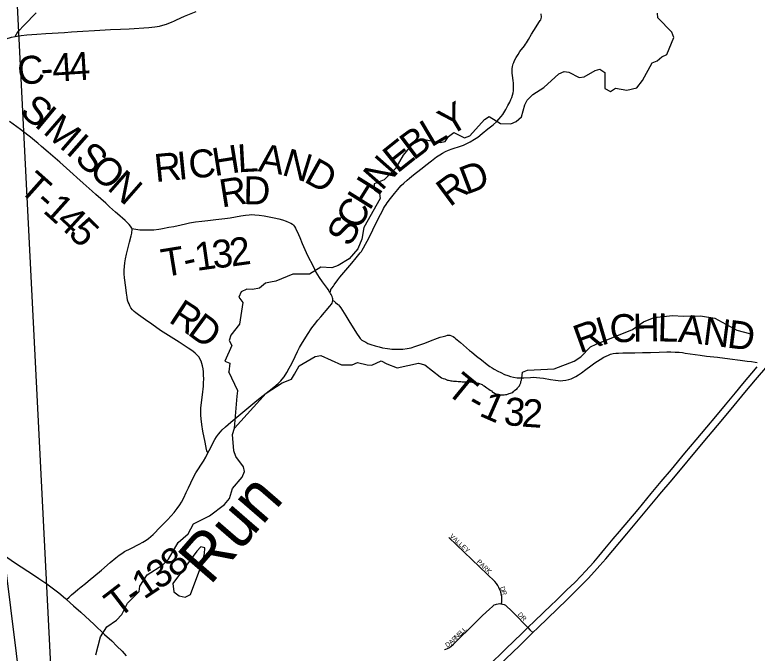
# Model space of a CAD drawing. Extents: x -19.5 to 44.1, y 0 to 22.
# Drawn here: x -16.656 to -15.147, y 16.812 to 18.108 of the extents above; entities that cross this region are included whole.
import ezdxf

# ---------------------------------------------------------------- set-up
doc = ezdxf.new("R2010")
doc.units = 0
for name, color, linetype in [('GM_X_County_Road', 7, 'Continuous'), ('GM_X_County_Road_Text', 7, 'Continuous'), ('GM_X_Minor_Lake', 7, 'Continuous'), ('GM_X_Minor_River', 7, 'Continuous'), ('GM_X_Minor_River_Text', 7, 'Continuous'), ('GM_X_State_Route', 7, 'Continuous'), ('GM_X_Township_Road', 7, 'Continuous'), ('GM_X_Township_Road_Text', 7, 'Continuous'), ('GM_X_Township_Subdivision', 7, 'Continuous'), ('GM_X_Township_Subdivision_Text', 7, 'Continuous'), ('GM_X_US_Route', 7, 'Continuous'), ('SH_Text', 7, 'Continuous')]:
    doc.layers.add(name, color=color, linetype=linetype)

msp = doc.modelspace()

# ---------------------------------------------------------------- linework, layer by layer
at = {"layer": 'GM_X_County_Road'}
for points in [[(-16.655, 18.0643), (-16.6513, 18.065), (-16.6427, 18.0663), (-16.6315, 18.0675), (-16.6111, 18.0691), (-16.5931, 18.0703), (-16.5548, 18.0728), (-16.5405, 18.0737), (-16.5176, 18.0753), (-16.494, 18.0767), (-16.4618, 18.0785), (-16.4413, 18.0793), (-16.4239, 18.0802), (-16.3836, 18.0827), (-16.3713, 18.0839), (-16.3622, 18.0855), (-16.355, 18.0873), (-16.348, 18.0896), (-16.3365, 18.0942), (-16.3325, 18.0959), (-16.3275, 18.0983), (-16.311, 18.1054), (-16.2876, 18.1155)], [(-16.8237, 18.0111), (-16.8025, 18.0178), (-16.7647, 18.0298), (-16.7263, 18.0425), (-16.7151, 18.0462), (-16.6944, 18.0528), (-16.6735, 18.0597), (-16.6626, 18.0629), (-16.655, 18.0643)]]:
    msp.add_lwpolyline(points, dxfattribs=at)
at = {"layer": 'GM_X_Minor_Lake'}
for points in [[(-16.3349, 16.9533), (-16.333, 16.9365), (-16.3218, 16.9279), (-16.3097, 16.9254), (-16.2989, 16.9312), (-16.2761, 16.9927), (-16.2708, 17.0135), (-16.2701, 17.0256), (-16.2777, 17.028), (-16.2862, 17.0191)], [(-16.2862, 17.0191), (-16.3349, 16.9533)]]:
    msp.add_lwpolyline(points, dxfattribs=at)
at = {"layer": 'GM_X_Minor_River'}
for points in [[(-15.9051, 17.7734), (-15.8808, 17.7974), (-15.8659, 17.8237), (-15.8477, 17.8458), (-15.8278, 17.8557), (-15.7918, 17.8494), (-15.7815, 17.8511), (-15.7745, 17.8613), (-15.7641, 17.8691), (-15.7423, 17.8588), (-15.7312, 17.8624), (-15.7018, 17.8961), (-15.6918, 17.902), (-15.6693, 17.8876), (-15.648, 17.8868), (-15.6369, 17.8916), (-15.6261, 17.9013), (-15.6196, 17.9255), (-15.6149, 17.9352), (-15.603, 17.9464), (-15.5807, 17.9605), (-15.5502, 17.9888), (-15.5399, 17.9932), (-15.53, 17.9919), (-15.5093, 17.9809), (-15.4991, 17.9826), (-15.4768, 17.9955), (-15.4669, 17.998), (-15.4572, 17.991), (-15.4573, 17.9591), (-15.4457, 17.9529), (-15.4353, 17.9595), (-15.4126, 17.9553), (-15.392, 17.9603), (-15.3807, 17.9749), (-15.3611, 18.011), (-15.3508, 18.015), (-15.3412, 18.0228), (-15.3312, 18.0276), (-15.3166, 18.0627), (-15.3206, 18.0734), (-15.3493, 18.102), (-15.3503, 18.1115)], [(-15.9051, 17.7734), (-15.9256, 17.7653), (-15.9251, 17.7531), (-15.9146, 17.7453), (-15.9137, 17.7354), (-15.9467, 17.6765), (-15.9509, 17.653), (-15.9589, 17.6334), (-15.9767, 17.6126), (-15.999, 17.599), (-16.0116, 17.5947), (-16.0343, 17.596), (-16.0573, 17.5816), (-16.0911, 17.5816), (-16.1255, 17.5676), (-16.1365, 17.5651), (-16.1464, 17.5635), (-16.1584, 17.5535), (-16.1732, 17.5504), (-16.1846, 17.5514), (-16.1961, 17.5459), (-16.2009, 17.5346), (-16.1927, 17.5242), (-16.1992, 17.4803), (-16.2167, 17.4575), (-16.2204, 17.447), (-16.2149, 17.437), (-16.2295, 17.405), (-16.219, 17.4006), (-16.2209, 17.3832)], [(-15.6257, 17.3704), (-15.6244, 17.3825), (-15.614, 17.3865), (-15.5601, 17.3894), (-15.5192, 17.405), (-15.5058, 17.4135), (-15.4864, 17.4337), (-15.4749, 17.4392), (-15.4008, 17.4694), (-15.3781, 17.485), (-15.3571, 17.4938), (-15.3198, 17.4977), (-15.2974, 17.4965), (-15.2625, 17.4967), (-15.2337, 17.4924), (-15.1885, 17.4681), (-15.1632, 17.4612)], [(-16.0879, 17.3788), (-16.0783, 17.3952), (-16.0457, 17.4147), (-16.0343, 17.4167), (-15.9918, 17.3975), (-15.9706, 17.3975), (-15.9599, 17.4022), (-15.9398, 17.3972), (-15.9304, 17.3966), (-15.9112, 17.4056)], [(-15.9112, 17.4056), (-15.9001, 17.3994), (-15.879, 17.3911), (-15.8359, 17.401), (-15.8227, 17.3977), (-15.7917, 17.3733)], [(-16.4911, 16.8084), (-16.482, 16.8451), (-16.4687, 16.8653), (-16.4491, 16.879), (-16.4386, 16.8905), (-16.4272, 16.9131), (-16.4035, 16.9373), (-16.4022, 16.9479), (-16.387, 16.9707), (-16.3554, 16.9913), (-16.3438, 17.0029), (-16.3242, 17.0366), (-16.3034, 17.0541), (-16.2927, 17.0747), (-16.2605, 17.0904), (-16.2297, 17.114), (-16.22, 17.126), (-16.2135, 17.146), (-16.1941, 17.1691), (-16.1893, 17.1808), (-16.191, 17.1903), (-16.2066, 17.2112), (-16.2109, 17.223), (-16.2133, 17.2558), (-16.2096, 17.2686), (-16.2042, 17.3335), (-16.2028, 17.3445), (-16.2209, 17.3832)], [(-16.2096, 17.2686), (-16.1449, 17.3398), (-16.1129, 17.3608), (-16.0934, 17.3683), (-16.0879, 17.3788)], [(-15.7917, 17.3733), (-15.7888, 17.3711), (-15.7854, 17.3695), (-15.782, 17.3687), (-15.7797, 17.3676), (-15.777, 17.3664), (-15.7748, 17.366), (-15.7721, 17.3656), (-15.7702, 17.3652), (-15.7672, 17.3648), (-15.7645, 17.3644), (-15.7615, 17.3644), (-15.7584, 17.3644), (-15.755, 17.3636), (-15.752, 17.3636), (-15.7493, 17.3636), (-15.747, 17.3632), (-15.7444, 17.3632), (-15.7409, 17.3631), (-15.7379, 17.3635), (-15.7348, 17.3631), (-15.7318, 17.3627), (-15.7291, 17.3627), (-15.7269, 17.3623), (-15.7246, 17.3619), (-15.7219, 17.3619), (-15.7193, 17.3611), (-15.7166, 17.3603), (-15.714, 17.3599), (-15.7064, 17.3572), (-15.7041, 17.3556), (-15.7022, 17.3549), (-15.6992, 17.3529), (-15.6965, 17.3507), (-15.6946, 17.3495), (-15.6927, 17.3483), (-15.6897, 17.346), (-15.6874, 17.3449), (-15.6852, 17.3422), (-15.6833, 17.3414), (-15.6799, 17.3391), (-15.6765, 17.338), (-15.6734, 17.3372), (-15.6708, 17.3372), (-15.6689, 17.3368), (-15.6658, 17.3367), (-15.6639, 17.3367), (-15.6613, 17.3367), (-15.6586, 17.3371), (-15.6559, 17.3374), (-15.6517, 17.3389), (-15.6487, 17.34), (-15.6464, 17.3404), (-15.6441, 17.3412), (-15.6426, 17.3434), (-15.6407, 17.3453), (-15.638, 17.3472), (-15.6361, 17.3479), (-15.6346, 17.3498), (-15.6338, 17.3517), (-15.6307, 17.3551), (-15.6299, 17.357), (-15.628, 17.3608), (-15.6276, 17.3638), (-15.6265, 17.3665), (-15.6257, 17.3704)]]:
    msp.add_lwpolyline(points, dxfattribs=at)
at = {"layer": 'GM_X_State_Route'}
for points in [[(-16.679, 17.0112), (-16.6547, 16.9949), (-16.618, 16.9709)], [(-16.618, 16.9709), (-16.6069, 16.9636), (-16.591, 16.9526), (-16.58, 16.9445), (-16.5668, 16.9341), (-16.553, 16.9226), (-16.5508, 16.9207), (-16.5368, 16.9081), (-16.522, 16.8949), (-16.495, 16.87), (-16.4738, 16.85), (-16.4591, 16.8366), (-16.4483, 16.8262), (-16.4379, 16.8156), (-16.4294, 16.8064)]]:
    msp.add_lwpolyline(points, dxfattribs=at)
at = {"layer": 'GM_X_Township_Road'}
for points in [[(-16.655, 18.0643), (-16.6525, 18.0689), (-16.6515, 18.0708), (-16.6499, 18.0732), (-16.6482, 18.0754), (-16.6367, 18.0876), (-16.6125, 18.1126)], [(-16.015, 17.5439), (-16.0147, 17.5465), (-16.014, 17.5489), (-16.0135, 17.5503), (-16.0115, 17.5534), (-16.0086, 17.5575), (-16.0068, 17.5598), (-15.9993, 17.5701), (-15.9952, 17.5755), (-15.9875, 17.5847), (-15.971, 17.6042), (-15.9623, 17.6148), (-15.9541, 17.6248), (-15.9517, 17.6278), (-15.9499, 17.6304), (-15.9471, 17.6351), (-15.9359, 17.656), (-15.9282, 17.6716), (-15.9168, 17.6951), (-15.909, 17.7106), (-15.9065, 17.7149), (-15.9044, 17.7184), (-15.9015, 17.7229), (-15.8991, 17.7267), (-15.8927, 17.7354), (-15.8844, 17.7456), (-15.8776, 17.7536), (-15.8747, 17.7569), (-15.8707, 17.7616), (-15.8654, 17.7668), (-15.859, 17.7726), (-15.8542, 17.7766), (-15.846, 17.7837), (-15.8399, 17.7884), (-15.8285, 17.7969), (-15.8207, 17.803), (-15.8095, 17.8119), (-15.7991, 17.8198), (-15.7925, 17.8243), (-15.7871, 17.8275), (-15.7811, 17.8307), (-15.7748, 17.8334), (-15.7672, 17.8361), (-15.7502, 17.8416), (-15.7445, 17.8436), (-15.7377, 17.8468), (-15.7304, 17.8506), (-15.7221, 17.8557), (-15.7152, 17.8602), (-15.706, 17.8675), (-15.6948, 17.8767), (-15.6841, 17.885), (-15.6766, 17.892), (-15.6725, 17.8964), (-15.6678, 17.9018), (-15.6644, 17.9062), (-15.658, 17.9164), (-15.6538, 17.9242), (-15.6503, 17.9312), (-15.6478, 17.9362), (-15.646, 17.9403), (-15.6444, 17.9452), (-15.6434, 17.9497), (-15.6427, 17.9541), (-15.6425, 17.9565), (-15.6425, 17.9584), (-15.6426, 17.9623), (-15.6427, 17.9647), (-15.6427, 17.9668), (-15.6429, 17.9697), (-15.6436, 17.9753), (-15.6448, 17.9849), (-15.6455, 17.9899), (-15.6456, 17.9949), (-15.6455, 17.9989), (-15.6447, 18.0033), (-15.6432, 18.0086), (-15.6421, 18.0115), (-15.6403, 18.0157), (-15.6369, 18.0221), (-15.6334, 18.0277), (-15.6294, 18.034), (-15.6201, 18.0456), (-15.6179, 18.0487), (-15.616, 18.0516), (-15.612, 18.0581), (-15.6059, 18.069), (-15.6014, 18.0766), (-15.5897, 18.0947), (-15.5884, 18.0967), (-15.5872, 18.0985), (-15.5862, 18.1011), (-15.5857, 18.1034), (-15.5858, 18.1058), (-15.5861, 18.1083), (-15.5867, 18.1104)], [(-16.4181, 17.6742), (-16.4183, 17.6749), (-16.4193, 17.677), (-16.4209, 17.6792), (-16.4236, 17.6824), (-16.426, 17.685), (-16.4286, 17.6873), (-16.4319, 17.6905), (-16.4372, 17.6953), (-16.4421, 17.6995), (-16.447, 17.7042), (-16.4512, 17.7079), (-16.4632, 17.7187), (-16.4712, 17.7256), (-16.4916, 17.7437), (-16.4985, 17.75), (-16.517, 17.7666), (-16.5301, 17.778), (-16.5375, 17.7846), (-16.5642, 17.8089), (-16.5739, 17.8176), (-16.5879, 17.8296), (-16.6017, 17.8412), (-16.6094, 17.8479), (-16.6153, 17.8528), (-16.6209, 17.8573), (-16.6443, 17.8753), (-16.6665, 17.8916)], [(-16.4181, 17.6742), (-16.4144, 17.6736), (-16.41, 17.6729), (-16.4061, 17.6723), (-16.4021, 17.6717), (-16.3983, 17.6715), (-16.3896, 17.6714), (-16.3809, 17.6715), (-16.3734, 17.6719), (-16.3636, 17.673), (-16.3593, 17.6735), (-16.3557, 17.6741), (-16.3429, 17.6768), (-16.3331, 17.6785), (-16.3182, 17.6818), (-16.3091, 17.6841), (-16.301, 17.686), (-16.2889, 17.6879), (-16.2759, 17.6892), (-16.2635, 17.6907), (-16.2476, 17.6924), (-16.2295, 17.6947), (-16.2186, 17.696), (-16.1969, 17.7001), (-16.1872, 17.7017), (-16.1799, 17.7025), (-16.1743, 17.7027), (-16.1681, 17.7025), (-16.1595, 17.7017), (-16.1492, 17.7001), (-16.1291, 17.6961), (-16.1196, 17.6942), (-16.1123, 17.6919), (-16.1046, 17.6895), (-16.0982, 17.6869), (-16.0948, 17.6855), (-16.0915, 17.6835), (-16.0896, 17.6815), (-16.0874, 17.6783), (-16.0855, 17.6748), (-16.0797, 17.6623), (-16.077, 17.6559), (-16.0722, 17.644), (-16.0609, 17.6196), (-16.05, 17.5976), (-16.044, 17.5856), (-16.0411, 17.5802), (-16.0378, 17.5749), (-16.0313, 17.5659), (-16.0215, 17.5522), (-16.0181, 17.5476), (-16.0169, 17.546), (-16.015, 17.5439)], [(-16.2635, 17.2185), (-16.2646, 17.2206), (-16.2658, 17.2228), (-16.2664, 17.2256), (-16.2693, 17.2401), (-16.2737, 17.2628), (-16.2756, 17.2762), (-16.2772, 17.2877), (-16.2778, 17.2951), (-16.278, 17.302), (-16.2778, 17.3091), (-16.2757, 17.3263), (-16.2746, 17.3367), (-16.2726, 17.3544), (-16.2722, 17.3612), (-16.2717, 17.3688), (-16.2722, 17.3764), (-16.2724, 17.3832), (-16.2733, 17.3896), (-16.2744, 17.3953), (-16.2756, 17.4001), (-16.2772, 17.4047), (-16.2797, 17.4098), (-16.2816, 17.4128), (-16.2839, 17.4158), (-16.2861, 17.4181), (-16.2894, 17.4212), (-16.2933, 17.4243), (-16.2981, 17.4276), (-16.3036, 17.4313), (-16.322, 17.4434), (-16.3599, 17.4674), (-16.3776, 17.4799), (-16.3905, 17.4888), (-16.4044, 17.4988), (-16.4099, 17.5031), (-16.4134, 17.5058), (-16.4165, 17.5089), (-16.4199, 17.5133), (-16.422, 17.5172), (-16.4237, 17.5212), (-16.4254, 17.525), (-16.4267, 17.5288), (-16.4279, 17.5351), (-16.4289, 17.543), (-16.4303, 17.5548), (-16.433, 17.574), (-16.4334, 17.5822), (-16.4337, 17.5896), (-16.4332, 17.5973), (-16.4321, 17.6046), (-16.4309, 17.6126), (-16.4288, 17.6225), (-16.4227, 17.6466), (-16.4193, 17.6596), (-16.4183, 17.6648), (-16.4179, 17.6676), (-16.4177, 17.6705), (-16.4177, 17.6728), (-16.4181, 17.6742)], [(-16.01, 17.5283), (-16.01, 17.5312), (-16.0104, 17.5337), (-16.0114, 17.5365), (-16.0133, 17.5401), (-16.0145, 17.5422), (-16.015, 17.5439)], [(-16.2635, 17.2185), (-16.2608, 17.2236), (-16.2494, 17.2459), (-16.2461, 17.2515), (-16.242, 17.2569), (-16.2381, 17.2613), (-16.2344, 17.2652), (-16.2278, 17.2712), (-16.2169, 17.2808), (-16.1923, 17.3013), (-16.1761, 17.3149), (-16.1644, 17.325), (-16.1513, 17.3351), (-16.139, 17.3446), (-16.1298, 17.3518), (-16.1205, 17.3598), (-16.1157, 17.3647), (-16.1125, 17.3684), (-16.1089, 17.3733), (-16.1035, 17.3817), (-16.0982, 17.3907), (-16.0933, 17.4), (-16.0862, 17.4145), (-16.0813, 17.4243), (-16.0786, 17.4298), (-16.0772, 17.4325), (-16.0731, 17.4395), (-16.061, 17.4593), (-16.0523, 17.4727), (-16.0469, 17.4796), (-16.0402, 17.488), (-16.0343, 17.4953), (-16.0159, 17.5164), (-16.0125, 17.5208), (-16.0113, 17.5229), (-16.0104, 17.5253), (-16.01, 17.5283)], [(-16.01, 17.5283), (-16.0071, 17.5267), (-16.0041, 17.5241), (-15.9999, 17.5205)], [(-15.9999, 17.5205), (-15.9994, 17.5201), (-15.9985, 17.5193), (-15.9962, 17.5164), (-15.9937, 17.513), (-15.9902, 17.5079), (-15.9832, 17.497), (-15.9771, 17.487), (-15.965, 17.4675), (-15.9604, 17.4598), (-15.9567, 17.4549), (-15.9539, 17.4512), (-15.9507, 17.4479), (-15.9468, 17.4456), (-15.9429, 17.4432), (-15.9384, 17.4411), (-15.9326, 17.4388), (-15.9238, 17.436), (-15.9156, 17.4339), (-15.9086, 17.4322), (-15.8988, 17.4304), (-15.8938, 17.4297), (-15.8897, 17.4294), (-15.8827, 17.4291), (-15.8749, 17.4291), (-15.8674, 17.4294), (-15.8586, 17.4306), (-15.8507, 17.4322), (-15.8431, 17.4344), (-15.8229, 17.4416), (-15.8114, 17.4459), (-15.7967, 17.4514), (-15.7914, 17.4534), (-15.7855, 17.4553), (-15.7803, 17.4566), (-15.7764, 17.4576), (-15.7722, 17.4576), (-15.7684, 17.4567), (-15.765, 17.4548), (-15.7624, 17.4527), (-15.7603, 17.4509), (-15.7571, 17.4482), (-15.7503, 17.4427), (-15.7322, 17.4269), (-15.7278, 17.4236), (-15.7178, 17.4152), (-15.7077, 17.4073), (-15.6961, 17.3984), (-15.6907, 17.3943), (-15.6862, 17.3913), (-15.6816, 17.3886), (-15.6745, 17.3848), (-15.6686, 17.3818), (-15.6611, 17.3781), (-15.6541, 17.3755), (-15.6487, 17.3739), (-15.6423, 17.3723), (-15.6352, 17.3713), (-15.6285, 17.3709), (-15.6219, 17.3709), (-15.6083, 17.372), (-15.6016, 17.3721), (-15.5958, 17.372), (-15.5888, 17.3713), (-15.5818, 17.3703), (-15.5674, 17.3679), (-15.5571, 17.366), (-15.5515, 17.3653), (-15.5471, 17.3652), (-15.5421, 17.3655), (-15.5365, 17.3663), (-15.5303, 17.3676), (-15.5255, 17.369), (-15.5214, 17.3708), (-15.5158, 17.3736), (-15.5104, 17.3769), (-15.5043, 17.3812), (-15.4955, 17.3881), (-15.4857, 17.3957), (-15.4776, 17.4014), (-15.4667, 17.4085), (-15.4593, 17.4129), (-15.4544, 17.4154), (-15.4498, 17.4172), (-15.4452, 17.4191), (-15.4404, 17.4203), (-15.4346, 17.4209), (-15.4291, 17.4213), (-15.4205, 17.4216), (-15.4102, 17.4215), (-15.4033, 17.4215), (-15.3961, 17.4218), (-15.3806, 17.4223), (-15.3645, 17.4227), (-15.3463, 17.4232), (-15.3312, 17.4236), (-15.3226, 17.4236), (-15.3144, 17.4234), (-15.3062, 17.423), (-15.2993, 17.4222), (-15.2941, 17.4214), (-15.2633, 17.417), (-15.2505, 17.4154), (-15.2279, 17.4127), (-15.2029, 17.4097), (-15.1823, 17.407), (-15.168, 17.4052), (-15.1587, 17.4039), (-15.1517, 17.4027), (-15.1472, 17.4021)], [(-16.5508, 16.9207), (-16.5454, 16.9256), (-16.5407, 16.93), (-16.533, 16.9365), (-16.5276, 16.9413), (-16.5213, 16.9463), (-16.5126, 16.9533), (-16.507, 16.958), (-16.4799, 16.9802), (-16.4621, 16.9956), (-16.4505, 17.0055), (-16.4436, 17.0108), (-16.4388, 17.0145), (-16.4329, 17.0182), (-16.4205, 17.0245), (-16.4031, 17.0332), (-16.396, 17.0369), (-16.3892, 17.0411), (-16.3842, 17.0447), (-16.3795, 17.0486), (-16.375, 17.0529), (-16.3602, 17.0682), (-16.3458, 17.0827), (-16.338, 17.0909), (-16.3319, 17.0976), (-16.3261, 17.1053), (-16.3209, 17.113), (-16.3174, 17.1183), (-16.3125, 17.1276), (-16.3078, 17.1378), (-16.3058, 17.1421), (-16.3033, 17.1475), (-16.2985, 17.1576), (-16.2907, 17.1731), (-16.2879, 17.178), (-16.2728, 17.2018), (-16.2678, 17.2101), (-16.2635, 17.2185)]]:
    msp.add_lwpolyline(points, dxfattribs=at)
at = {"layer": 'GM_X_Township_Subdivision'}
for points in [[(-15.6667, 16.9121), (-15.6662, 16.917), (-15.6662, 16.9218), (-15.6666, 16.9266), (-15.6674, 16.9314), (-15.6686, 16.9361), (-15.6702, 16.9407), (-15.6722, 16.9451), (-15.6745, 16.9494), (-15.6772, 16.9534), (-15.6802, 16.9572), (-15.7741, 17.0469)], [(-15.7826, 16.8189), (-15.7798, 16.8197), (-15.777, 16.8209), (-15.7737, 16.8227), (-15.7702, 16.8253), (-15.7647, 16.8302), (-15.7571, 16.8376), (-15.7504, 16.8441), (-15.7348, 16.8592), (-15.7101, 16.8838), (-15.7055, 16.888), (-15.6915, 16.9012), (-15.6856, 16.9068), (-15.6817, 16.9097), (-15.6794, 16.9108), (-15.6771, 16.9116), (-15.674, 16.9123), (-15.6709, 16.9124), (-15.6685, 16.9123), (-15.6667, 16.9121)], [(-15.6667, 16.9121), (-15.6648, 16.9116), (-15.6619, 16.9106), (-15.6591, 16.9091), (-15.6562, 16.9068), (-15.648, 16.8992), (-15.6308, 16.8819), (-15.624, 16.8749), (-15.6133, 16.8637)], [(-15.6133, 16.8637), (-15.6091, 16.8594), (-15.6033, 16.8535)]]:
    msp.add_lwpolyline(points, dxfattribs=at)
at = {"layer": 'GM_X_US_Route'}
for points in [[(-15.6942, 16.7853), (-15.658, 16.8203), (-15.6259, 16.8514), (-15.6133, 16.8637), (-15.5992, 16.8775), (-15.566, 16.9093), (-15.5562, 16.9189), (-15.5339, 16.9404), (-15.5183, 16.9556), (-15.5051, 16.9689), (-15.4961, 16.9783), (-15.4795, 16.9969), (-15.4689, 17.009), (-15.4572, 17.0236), (-15.4398, 17.0438), (-15.4271, 17.0591), (-15.3895, 17.1038), (-15.3628, 17.1358), (-15.3426, 17.1602), (-15.3218, 17.1849), (-15.2942, 17.2177), (-15.2715, 17.2449), (-15.2495, 17.271), (-15.2316, 17.2925), (-15.2117, 17.3164), (-15.1913, 17.3406), (-15.1763, 17.3588), (-15.1472, 17.3937)], [(-15.348, 17.1312), (-15.3451, 17.1346), (-15.3204, 17.1641), (-15.257, 17.2399), (-15.2284, 17.2743), (-15.2005, 17.3076), (-15.1725, 17.341), (-15.1506, 17.3672), (-15.1261, 17.3964)], [(-15.5279, 16.9264), (-15.5079, 16.9462), (-15.4909, 16.9634), (-15.4777, 16.9774), (-15.467, 16.9895), (-15.4553, 17.0032), (-15.4124, 17.054), (-15.348, 17.1312)], [(-15.8731, 16.5813), (-15.8723, 16.5818), (-15.8717, 16.5822), (-15.871, 16.5828), (-15.8704, 16.5835), (-15.8699, 16.5842), (-15.8691, 16.5854), (-15.8673, 16.5881), (-15.8579, 16.6012), (-15.8517, 16.609), (-15.8452, 16.6174), (-15.8366, 16.6268), (-15.8301, 16.6335), (-15.8237, 16.6399), (-15.7837, 16.6789), (-15.7301, 16.7308), (-15.6965, 16.7631), (-15.659, 16.7995), (-15.63, 16.8275), (-15.6064, 16.8505), (-15.6033, 16.8535), (-15.593, 16.8634), (-15.5335, 16.9208), (-15.5279, 16.9264)]]:
    msp.add_lwpolyline(points, dxfattribs=at)
at = {"layer": 'SH_Text'}
msp.add_lwpolyline([(-16.7391, 19.8563), (-16.538, 15.8887), (-17.0308, 19.8566)], close=True, dxfattribs=at)

# ---------------------------------------------------------------- texts
at = {"layer": 'GM_X_County_Road_Text'}
for s, rotation, p in [('C', 7.0902, (-16.6472, 17.965)), ('4', 3.5982, (-16.5785, 17.9722)), ('4', 3.5775, (-16.5436, 17.9744)), ('-', 3.6947, (-16.6017, 17.9707))]:
    msp.add_text(s, height=0.0568, rotation=rotation, dxfattribs=at).set_placement(p)
at = {"layer": 'GM_X_Minor_River_Text'}
msp.add_text('Run', height=0.09469, rotation=49.0709, dxfattribs=at).set_placement((-16.2593, 16.9478))
at = {"layer": 'GM_X_Township_Road_Text'}
for s, rotation, p in [('S', 321.8856, (-16.6482, 17.9071)), ('I', 320.3369, (-16.6184, 17.8837)), ('Y', 31.1401, (-15.773, 17.8604)), ('M', 319.0216, (-16.6007, 17.8691)), ('L', 30.7411, (-15.8099, 17.8385)), ('B', 36.8016, (-15.8459, 17.8114)), ('I', 318.6511, (-16.5542, 17.8287)), ('S', 318.6462, (-16.5367, 17.8133)), ('H', 9.1377, (-16.25, 17.7806)), ('L', 3.1729, (-16.2022, 17.7884)), ('E', 38.5668, (-15.8788, 17.7852)), ('R', 5.7156, (-16.3698, 17.7685)), ('I', 5.7144, (-16.3233, 17.7731)), ('C', 5.7441, (-16.3001, 17.7754)), ('A', 351.4294, (-16.1628, 17.7909)), ('N', 343.0098, (-16.1155, 17.7839)), ('O', 318.655, (-16.5079, 17.7879)), ('D', 330.9604, (-16.0706, 17.7705)), ('N', 48.6808, (-15.9099, 17.7494)), ('D', 20.8882, (-15.7382, 17.7428)), ('T', 318.3337, (-16.6499, 17.7524)), ('N', 318.7949, (-16.4702, 17.7548)), ('R', 36.5198, (-15.7721, 17.717)), ('R', 9.0536, (-16.2354, 17.7169)), ('D', 358.8415, (-16.192, 17.724)), ('H', 57.9969, (-15.935, 17.709)), ('-', 318.2945, (-16.6182, 17.7242)), ('1', 318.111, (-16.6008, 17.7087)), ('C', 61.6158, (-15.9567, 17.6688)), ('4', 317.4589, (-16.5749, 17.6854)), ('5', 315.2355, (-16.5495, 17.6622)), ('S', 61.6391, (-15.9749, 17.635)), ('1', 8.1824, (-16.2863, 17.5881)), ('3', 6.1839, (-16.2522, 17.593)), ('2', 7.9454, (-16.2155, 17.597)), ('T', 9.1978, (-16.3536, 17.5756)), ('-', 12.7823, (-16.3079, 17.5831)), ('R', 326.7873, (-16.3455, 17.4857)), ('D', 323.666, (-16.3072, 17.4606)), ('C', 3.2411, (-15.4458, 17.442)), ('H', 0.8743, (-15.3999, 17.4446)), ('L', 358.3498, (-15.3505, 17.4453)), ('A', 354.0882, (-15.3092, 17.4442)), ('R', 19.805, (-15.5079, 17.4204)), ('I', 16.4301, (-15.4648, 17.436)), ('N', 352.7205, (-15.2598, 17.4391)), ('D', 352.7471, (-15.2101, 17.4328)), ('T', 320.711, (-15.7821, 17.342)), ('1', 336.2896, (-15.7145, 17.295)), ('3', 354.0591, (-15.664, 17.276)), ('-', 330.9089, (-15.7401, 17.3089)), ('2', 356.1062, (-15.627, 17.2722)), ('8', 40.2674, (-16.3298, 16.9629)), ('3', 33.9672, (-16.3642, 16.9392)), ('1', 33.8315, (-16.3934, 16.9197)), ('T', 37.4784, (-16.4456, 16.8811)), ('-', 34.476, (-16.4125, 16.9065))]:
    msp.add_text(s, height=0.0568, rotation=rotation, dxfattribs=at).set_placement(p)
at = {"layer": 'GM_X_Township_Subdivision_Text'}
for s, rotation, p in [('VALLEY', 317.1764, (-15.7731, 17.0482)), ('PARK', 315.853, (-15.7181, 16.9965)), ('D', 290.7582, (-15.6702, 16.9451)), ('R', 286.0455, (-15.6673, 16.9375)), ('DR', 312.8801, (-15.6347, 16.8898)), ('N', 44.171, (-15.7574, 16.8394)), ('E', 44.1596, (-15.7514, 16.8452)), ('L', 44.1769, (-15.7467, 16.8499)), ('L', 44.1596, (-15.7419, 16.8545)), ('D', 33.7386, (-15.7774, 16.8228)), ('A', 42.2764, (-15.7692, 16.8284)), ('R', 44.0141, (-15.7628, 16.8342))]:
    msp.add_text(s, height=0.00947, rotation=rotation, dxfattribs=at).set_placement(p)

doc.saveas('drawing.dxf')
